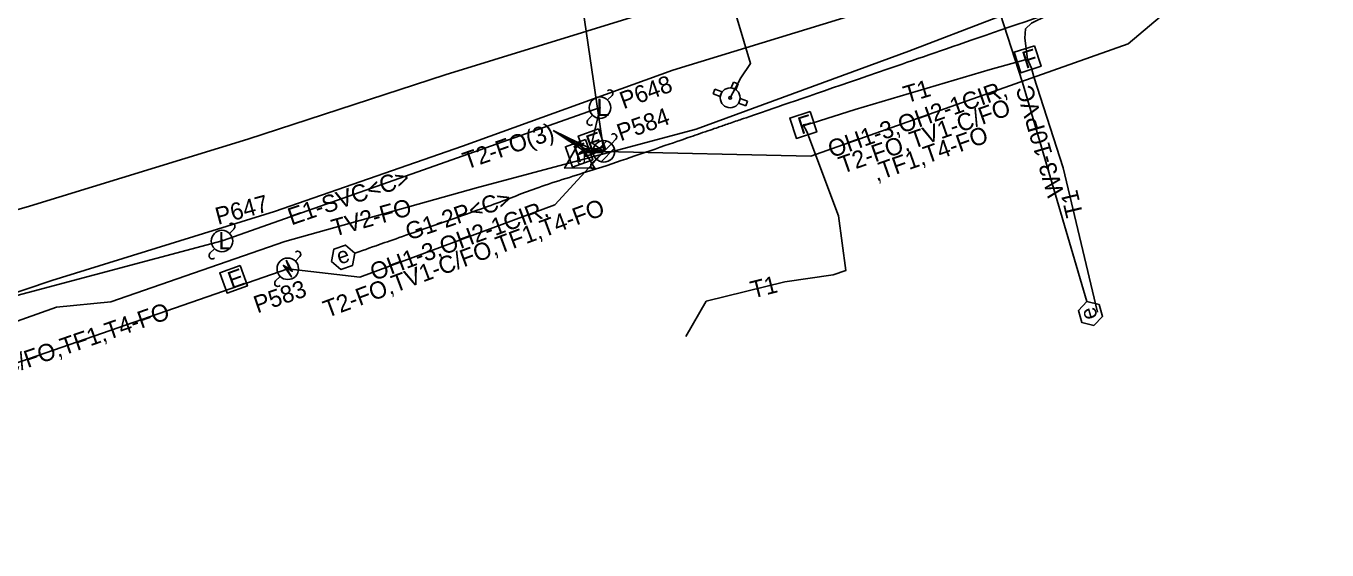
# Model space of a CAD drawing. Extents: x 2336688 to 2352634, y 362473 to 369571.
# Drawn here: x 2350284.9 to 2350587.4, y 368303.5 to 368425.3 of the extents above; entities that cross this region are included whole.
import ezdxf

# ---------------------------------------------------------------- set-up
doc = ezdxf.new("R2010")
doc.units = 0
for name, color, linetype in [('RD_EX_DV_Prop', 7, 'Continuous'), ('RD_EX_DV_TX_Prop', 7, 'Continuous'), ('RD_EX_RW', 7, 'Continuous'), ('RD_EX_RW_TX', 7, 'Continuous'), ('RD_HC_CL_Rel', 7, 'Continuous'), ('RD_HC_Data_Tic', 7, 'Continuous'), ('RD_PD_CstnLmt', 7, 'Continuous'), ('RD_PD_Final_TrvlWay', 7, 'Continuous'), ('RD_PD_PatLn2', 7, 'Continuous'), ('RD_PD_PatLn3', 7, 'Continuous'), ('RD_PD_PatLn4', 7, 'Continuous'), ('RD_SHT_ShtClip', 7, 'Continuous'), ('RD_Sketch2', 7, 'Continuous'), ('RD_Sketch5', 7, 'Continuous')]:
    doc.layers.add(name, color=color, linetype=linetype)

msp = doc.modelspace()

# ---------------------------------------------------------------- linework, layer by layer
at = {"layer": 'RD_EX_RW'}
for p, q in [((2350407.46, 368401), (2350415.25, 368395.87)), ((2350415.69, 368396.27), (2350407.46, 368401)), ((2350407.46, 368401), (2350416.2, 368396.71))]:
    msp.add_line(p, q, dxfattribs=at)
at = {"layer": 'RD_EX_RW_TX'}
for points in [[(2350438.31, 368353.14), (2350443.06, 368361.29), (2350461.37, 368365.85), (2350472.57, 368367.45), (2350475.55, 368368.48), (2350473.81, 368381.16), (2350466.45, 368400.79), (2350465.63, 368402.3), (2350467.73, 368402.72), (2350477.74, 368405.85), (2350509.1, 368415.22), (2350517.8, 368417.58), (2350517.14, 368422.45), (2350517.32, 368424.65), (2350518.71, 368425.94), (2350533.4, 368433.24), (2350568.35, 368450.8), (2350585.17, 368458.19), (2350631.55, 368472.55)], [(2350577.9, 368452.25), (2350577.71, 368453.44), (2350574.65, 368455.11), (2350567.18, 368452.41), (2350530.66, 368434.99), (2350490.17, 368419.45), (2350440.7, 368401.32), (2350389.67, 368387.65), (2350345.03, 368375.16), (2350304.59, 368361.14), (2350291.95, 368359.89), (2350248.07, 368344.34), (2350203.54, 368331.65), (2350161.47, 368317.74), (2350118.87, 368303.47)], [(2350517.8, 368417.58), (2350518.69, 368415.48), (2350519.22, 368413.5), (2350526.09, 368392.32), (2350534.05, 368358.79)], [(2350419.25, 368396.14), (2350418.13, 368396.72), (2350414.98, 368396.71), (2350413.49, 368395.71)], [(2350413.49, 368395.71), (2350415.06, 368396.27), (2350418.37, 368396.28), (2350419.25, 368396.14)], [(2350419.25, 368396.14), (2350418.61, 368395.87), (2350415.13, 368395.87), (2350413.49, 368395.71)]]:
    msp.add_lwpolyline(points, dxfattribs=at)
for points in [[(2350519.42, 368420.72), (2350514.66, 368419.19), (2350516.19, 368414.43), (2350520.95, 368415.96)], [(2350467.25, 368405.45), (2350462.49, 368403.91), (2350464.02, 368399.15), (2350468.78, 368400.69)], [(2350415.01, 368398.9), (2350410.3, 368397.22), (2350411.97, 368392.51), (2350416.69, 368394.19)]]:
    msp.add_lwpolyline(points, close=True, dxfattribs=at)
at = {"layer": 'RD_HC_CL_Rel'}
msp.add_lwpolyline([(2350361.36, 368372.49), (2350359.17, 368374.37), (2350356.44, 368373.41), (2350355.91, 368370.58), (2350358.1, 368368.69), (2350360.82, 368369.65)], close=True, dxfattribs=at)
msp.add_open_spline([(2350361.36, 368372.49), (2350363.93, 368373.39), (2350366.51, 368374.3), (2350381.17, 368379.43), (2350395.35, 368384.35), (2350403.79, 368387.84), (2350418.76, 368392.43), (2350425.89, 368394.88), (2350436.61, 368398.57), (2350440.18, 368399.8), (2350445.54, 368401.64), (2350447.33, 368402.26), (2350450.91, 368403.49), (2350452.7, 368404.1), (2350483.05, 368414.54), (2350511.62, 368424.37), (2350540.18, 368434.2)], degree=3, dxfattribs=at)
at = {"layer": 'RD_HC_Data_Tic'}
for p, q in [((2350420.12, 368408.11), (2350421.17, 368409.18)), ((2350415.57, 368403.46), (2350416.62, 368404.54)), ((2350416.83, 368395.49), (2350419.89, 368398.55)), ((2350421.01, 368397.91), (2350422.07, 368398.97)), ((2350417.48, 368394.37), (2350421.01, 368397.91)), ((2350418.6, 368393.73), (2350421.66, 368396.79)), ((2350416.42, 368393.31), (2350417.48, 368394.37)), ((2350332.2, 368377.09), (2350333.25, 368378.16)), ((2350327.65, 368372.45), (2350328.7, 368373.52)), ((2350347.52, 368370.61), (2350348.58, 368371.68)), ((2350342.93, 368366.02), (2350343.99, 368367.08))]:
    msp.add_line(p, q, dxfattribs=at)
msp.add_lwpolyline([(2350345.36, 368370.86), (2350346.19, 368368.84), (2350344.73, 368369.64), (2350346.6, 368366.96), (2350346.6, 368366.96), (2350345.4, 368369.06), (2350346.79, 368368.26)], close=True, dxfattribs=at)
for centre in [(2350418.37, 368406.32), (2350419.25, 368396.14), (2350330.45, 368375.3), (2350345.75, 368368.85)]:
    msp.add_circle(centre, 2.5, dxfattribs=at)
for centre, start, end in [((2350420.63, 368409.7), 315.5955, 135.5955), ((2350416.11, 368402.94), 135.5955, 315.5955), ((2350421.54, 368399.5), 315, 135), ((2350416.95, 368392.78), 135, 315), ((2350332.71, 368378.69), 315.5955, 135.5955), ((2350328.19, 368371.92), 135.5955, 315.5955), ((2350348.05, 368372.21), 315, 135), ((2350343.46, 368365.49), 135, 315)]:
    msp.add_arc(centre, 0.75, start, end, dxfattribs=at)
at = {"layer": 'RD_PD_CstnLmt'}
msp.add_lwpolyline([(2350531.6, 368361.22), (2350529.61, 368359.13), (2350530.43, 368356.36), (2350533.23, 368355.68), (2350535.22, 368357.77), (2350534.41, 368360.54)], close=True, dxfattribs=at)
at = {"layer": 'RD_PD_Final_TrvlWay'}
msp.add_lwpolyline([(2350419.25, 368396.14), (2350416.48, 368398.17), (2350418.37, 368406.32), (2350330.49, 368375.37), (2350224.73, 368347.2), (2350123.83, 368313.64), (2350116.09, 368310.82)], dxfattribs=at)
for points in [[(2350418, 368401.36), (2350413.29, 368399.69), (2350414.96, 368394.97), (2350419.67, 368396.64)], [(2350334.66, 368369.59), (2350329.95, 368367.9), (2350331.64, 368363.19), (2350336.35, 368364.88)]]:
    msp.add_lwpolyline(points, close=True, dxfattribs=at)
at = {"layer": 'RD_PD_PatLn3'}
msp.add_lwpolyline([(2350413.51, 368398.28), (2350410.12, 368392.23), (2350417.05, 368392.33)], close=True, dxfattribs=at)
at = {"layer": 'RD_SHT_ShtClip'}
for p, q in [((2350419.25, 368396.14), (2350399.92, 368528.37)), ((2350171.37, 368308.42), (2350345.75, 368368.85))]:
    msp.add_line(p, q, dxfattribs=at)
for points in [[(2350419.25, 368396.14), (2350467.37, 368395.02), (2350541.18, 368421.12), (2350577.9, 368452.25)], [(2350345.75, 368368.85), (2350362.48, 368366.9), (2350407.85, 368383.75), (2350419.25, 368396.14)]]:
    msp.add_lwpolyline(points, dxfattribs=at)
at = {"layer": 'RD_Sketch2'}
for p, q in [((2350445.08, 368410.59), (2350444.69, 368409.5)), ((2350446.77, 368409.97), (2350445.08, 368410.59)), ((2350449.4, 368412.27), (2350448.9, 368410.89)), ((2350450.49, 368411.88), (2350449.4, 368412.27)), ((2350449.98, 368410.47), (2350450.49, 368411.88)), ((2350444.69, 368409.5), (2350446.34, 368408.9)), ((2350450.58, 368407.36), (2350452.29, 368406.74)), ((2350452.68, 368407.83), (2350450.94, 368408.46)), ((2350452.29, 368406.74), (2350452.68, 368407.83))]:
    msp.add_line(p, q, dxfattribs=at)
for points in [[(2351042.86, 368655.18), (2350995.25, 368636.19), (2350951.94, 368625.72), (2350904.41, 368609.66), (2350850.2, 368589.13), (2350807.88, 368571.45), (2350758.45, 368549.2), (2350717.62, 368531.89), (2350669.89, 368513.41), (2350618.71, 368497.66), (2350574.37, 368479.11), (2350524.2, 368457.7), (2350508, 368452.18), (2350504.2, 368450.53), (2350448.23, 368434.31), (2350382.35, 368413.96), (2350336.49, 368399.02), (2350285.67, 368383.39), (2350239.06, 368369.9), (2350196.44, 368356.53), (2350109.57, 368328)], [(2350504.2, 368450.53), (2350504.56, 368449.6), (2350516.6, 368412.18), (2350531.6, 368361.22)], [(2350448.23, 368434.31), (2350448.51, 368433), (2350453.38, 368416.62), (2350451.15, 368413.25), (2350448.63, 368408.6)]]:
    msp.add_lwpolyline(points, dxfattribs=at)
for radius in [2.31, 0.289]:
    msp.add_circle((2350448.63, 368408.6), radius, dxfattribs=at)
for start, end in [(54.287, 83.2543), (143.3802, 172.3565), (327.7265, 356.7028)]:
    msp.add_arc((2350448.63, 368408.6), 2.31, start, end, dxfattribs=at)
at = {"layer": 'RD_Sketch5'}
msp.add_lwpolyline([(2350116.54, 368309.62), (2350157.85, 368325.74), (2350201.04, 368338.25), (2350246.21, 368351.09), (2350290.88, 368366.1), (2350342.68, 368382.19), (2350386.37, 368397.34), (2350435.33, 368415.03), (2350480.68, 368428.89), (2350526.02, 368446.27), (2350580.59, 368465.31), (2350628.33, 368480.35), (2350681.49, 368498.77), (2350722.35, 368517.44), (2350762.63, 368535.33), (2350810.28, 368554.98), (2350857.34, 368575.64), (2350905.94, 368596.06), (2350950.65, 368611.89), (2350997.52, 368629.24), (2351044.06, 368648.74)], dxfattribs=at)

# ---------------------------------------------------------------- texts
at = {"layer": 'RD_EX_DV_Prop'}
msp.add_text('E1-SVC<C>', height=4, rotation=18.8849, dxfattribs=at).set_placement((2350346.59, 368378.92))
at = {"layer": 'RD_EX_DV_TX_Prop'}
for s, rotation, p in [('P648', 20.0284, (2350423.84, 368405.94)), ('P584', 19.4748, (2350423.15, 368398.47)), ('P647', 14.9152, (2350329.51, 368379.05)), ('P583', 19.1115, (2350338.67, 368358.48))]:
    msp.add_text(s, height=4, rotation=rotation, dxfattribs=at).set_placement(p)
at = {"layer": 'RD_EX_RW'}
for s, rotation, p in [('T1', 16.635, (2350489.62, 368407.31)), ('T2-FO(3)', 19.0885, (2350387.28, 368391.9)), ('T1', 103.3511, (2350530.74, 368381.36)), ('TV2-FO', 15.6359, (2350356.57, 368376.31)), ('T1', 13.9928, (2350453.9, 368361.93))]:
    msp.add_text(s, height=4, rotation=rotation, dxfattribs=at).set_placement(p)
at = {"layer": 'RD_EX_RW_TX'}
for rotation, p in [(17.866, (2350517.34, 368415.32)), (17.866, (2350465.17, 368400.05)), (19.5618, (2350413.09, 368393.44))]:
    msp.add_text('F', height=4, rotation=rotation, dxfattribs=at).set_placement(p)
at = {"layer": 'RD_HC_CL_Rel'}
msp.add_text('e', height=3.75, rotation=19.3276, dxfattribs=at).set_placement((2350357.85, 368369.77))
at = {"layer": 'RD_HC_Data_Tic'}
for p in [(2350417.58, 368404.38), (2350329.66, 368373.36)]:
    msp.add_text('L', height=4, rotation=0.5955, dxfattribs=at).set_placement(p)
at = {"layer": 'RD_PD_CstnLmt'}
for s, height, p in [('W3-10PVC', 4, (2350526.37, 368386.25)), ('e', 3.75, (2350534.14, 368357.58))]:
    msp.add_text(s, height=height, rotation=106.4046, dxfattribs=at).set_placement(p)
at = {"layer": 'RD_PD_Final_TrvlWay'}
for rotation, p in [(19.4982, (2350416.01, 368395.87)), (19.7349, (2350332.68, 368364.1))]:
    msp.add_text('E', height=4, rotation=rotation, dxfattribs=at).set_placement(p)
at = {"layer": 'RD_PD_PatLn2'}
msp.add_text('G1-2P<C>', height=4, rotation=18.7308, dxfattribs=at).set_placement((2350373.93, 368375.4))
at = {"layer": 'RD_PD_PatLn3'}
msp.add_text('U', height=2.4, rotation=0.7793, dxfattribs=at).set_placement((2350412.82, 368393.07))
at = {"layer": 'RD_PD_PatLn4'}
for s, rotation, p in [('OH1-3,OH2-1CIR,', 19.315, (2350472.23, 368394.58)), ('TV1-C/FO', 19.315, (2350491.2, 368396.69)), (',TF1,T4-FO', 19.315, (2350482.64, 368389.15)), ('T2-FO,', 19.315, (2350474.74, 368390.92)), ('T2-FO,TV1-C/FO,TF1,T4-FO', 20.3737, (2350354.9, 368357.39)), ('OH1-3,OH2-1CIR,', 20.3737, (2350365.81, 368366)), ('OH1-3,OH2-1CIR,T2-FO,TV1-C/FO,TF1,T4-FO', 19.1115, (2350211.93, 368320.36))]:
    msp.add_text(s, height=4, rotation=rotation, dxfattribs=at).set_placement(p)

doc.saveas('drawing.dxf')
